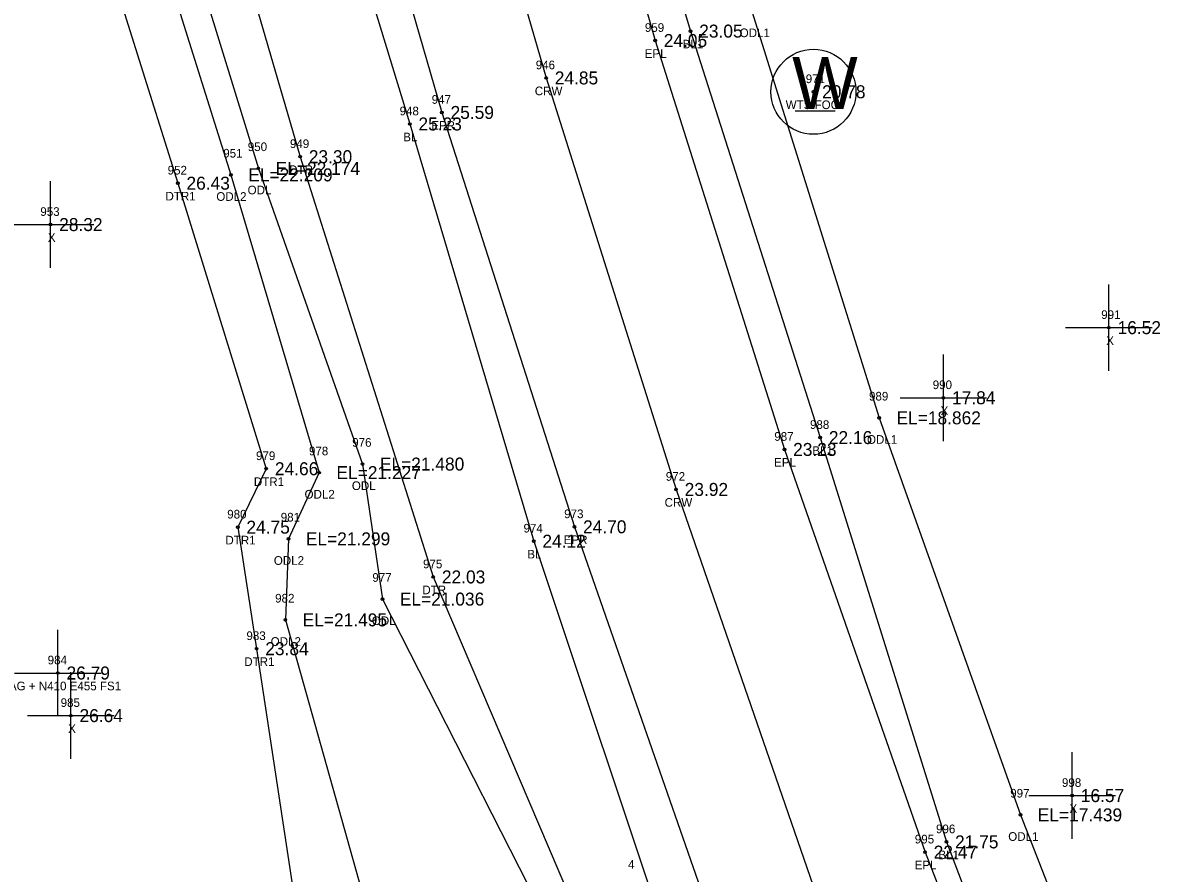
# Model space of a CAD drawing. Extents: x 2042211 to 2045853, y 303080 to 309569.
# Drawn here: x 2042861.3 to 2042993, y 306702 to 306800.2 of the extents above; entities that cross this region are included whole.
import ezdxf

# ---------------------------------------------------------------- set-up
doc = ezdxf.new("R2010")
doc.units = 0
for name, color, linetype in [('BR_500YR_SCOUR', 7, 'Continuous'), ('RD_DTM_BkLn1', 7, 'Continuous'), ('RD_DTM_BkLn_txCode', 7, 'Continuous'), ('RD_EX_H2O', 7, 'Continuous'), ('RD_EX_H2O_txCode', 7, 'Continuous'), ('RD_EX_Misc', 7, 'Continuous'), ('RD_EX_Misc_txCode', 7, 'Continuous'), ('RD_EX_Road', 7, 'Continuous'), ('RD_EX_Road_txCode', 7, 'Continuous'), ('RD_EX_TX_H2O_ELEV', 7, 'Continuous'), ('RD_EX_TX_Misc_ELEV', 7, 'Continuous'), ('RD_EX_TX_Road_ELEV', 7, 'Continuous'), ('RD_EX_TX_UT_ELEV', 7, 'Continuous'), ('RD_EX_UT_txCode', 7, 'Continuous'), ('RD_HC_Survey_ELEV', 7, 'Continuous'), ('RD_HC_Survey_txCode', 7, 'Continuous'), ('RD_SMD_Locator', 7, 'Continuous')]:
    doc.layers.add(name, color=color, linetype=linetype)

msp = doc.modelspace()

# ---------------------------------------------------------------- linework, layer by layer
at = {"layer": 'BR_500YR_SCOUR'}
msp.add_line((2042950.59, 306790.07), (2042955.22, 306790.07), dxfattribs=at)
for radius in [4.91, 0.15]:
    msp.add_circle((2042952.72, 306792.28), radius, dxfattribs=at)
at = {"layer": 'RD_DTM_BkLn1'}
for points in [[(2042839.81, 307329.37), (2042840.93, 307280.46), (2042843.39, 307231.17), (2042846.87, 307181.66), (2042851.76, 307132.07), (2042857.83, 307083.36), (2042865.03, 307034.36), (2042873.56, 306985.67), (2042883.71, 306937.59), (2042895.32, 306889.27), (2042908.01, 306841.41), (2042921.81, 306793.88), (2042936.83, 306746.34), (2042953.05, 306699.55), (2042970.36, 306653.6), (2042989.25, 306607.34), (2043009.36, 306561.99), (2043030.44, 306517.39), (2043052.89, 306472.91), (2043076.3, 306429.26), (2043100.43, 306386.21)], [(2042857.66, 307329.64), (2042861.09, 307281.84), (2042862.27, 307232.19), (2042866.29, 307183.84), (2042870.56, 307134.28), (2042875.48, 307086.26), (2042882.95, 307037.68), (2042891.21, 306988.93), (2042900.82, 306941.19), (2042911.81, 306893.75), (2042924.4, 306846), (2042938.51, 306799.29), (2042953.5, 306752.33), (2042968.09, 306705.62), (2042985.63, 306659.36), (2043004.49, 306613.62), (2043024.61, 306569.26), (2043045.97, 306525.25), (2043068.43, 306480.84), (2043092.42, 306438.64), (2043116.55, 306395.12)], [(2042839.17, 307095.11), (2042841.19, 307080.52), (2042848.71, 307031.33), (2042857.64, 306982.34), (2042868.25, 306933.78), (2042879.62, 306884.9), (2042891.37, 306836.61), (2042906.05, 306788.56), (2042920.38, 306740.36), (2042936.3, 306692.68), (2042942.2, 306670.77), (2042952.72, 306646.49), (2042972.88, 306600.44), (2042993.94, 306554.96), (2043015.19, 306509.48), (2043037.06, 306464.5), (2043060.22, 306420.45)]]:
    msp.add_lwpolyline(points, dxfattribs=at)
at = {"layer": 'RD_EX_H2O'}
for points in [[(2042866.82, 307329.93), (2042876.23, 307282.16), (2042878.43, 307232.86), (2042875.08, 307184.77), (2042887.19, 307136.65), (2042884.32, 307120.02), (2042882.74, 307087.49), (2042892.51, 307039.16), (2042896.41, 306990.42), (2042899.37, 306973.37), (2042910.05, 306942.23), (2042920.75, 306896.67), (2042927.15, 306846.78), (2042945.6, 306801.59), (2042960.32, 306754.61), (2042976.65, 306708.74), (2042994.63, 306662.76), (2043013.3, 306616.98), (2043029.17, 306571.91), (2043050.77, 306528.53)], [(2042809.74, 307126.16), (2042806.56, 307122.63), (2042790.31, 307116.78), (2042788.49, 307114.78), (2042791.89, 307113.57), (2042804.81, 307114.94), (2042810.25, 307075.93), (2042820.25, 307025.92), (2042830.4, 306977.21), (2042843.29, 306928.12), (2042852.91, 306878.24), (2042864.55, 306828.43), (2042879.23, 306781.72), (2042889.45, 306748.73), (2042886.16, 306741.98), (2042888.34, 306727.94), (2042896.13, 306676.35), (2042885.67, 306665.43), (2042857.25, 306612.72)], [(2042809.74, 307126.16), (2042815.01, 307124.31), (2042821.79, 307118.99), (2042825.8, 307110.2), (2042827.88, 307100.21), (2042830.08, 307078.71), (2042836.25, 307029.11), (2042845.48, 306980.04), (2042852.07, 306929.46), (2042864.58, 306881.26), (2042879.31, 306833.06), (2042893.37, 306784.78), (2042908.76, 306736.23), (2042928.77, 306689.39), (2042938.94, 306669.11)], [(2042810.02, 307117.36), (2042813.87, 307076.18), (2042825.65, 307027), (2042835.99, 306978.45), (2042846.19, 306929.27), (2042857.5, 306879.97), (2042870.3, 306830.67), (2042885.37, 306782.68), (2042895.57, 306748.28), (2042892.03, 306740.63), (2042891.66, 306731.27), (2042905.95, 306680.58), (2042906.87, 306643.18), (2042864.97, 306605.63)], [(2042812.2, 307117.75), (2042817.66, 307076.99), (2042828.97, 307027.39), (2042840.42, 306978.95), (2042848.44, 306929.66), (2042859.84, 306880.36), (2042873.68, 306831.67), (2042888.54, 306783.43), (2042900.59, 306749.27), (2042902.9, 306733.67), (2042926.04, 306688.21), (2042936.45, 306668.37), (2042947.44, 306643.99), (2042966.18, 306597.91), (2042985.34, 306551.14), (2042987.61, 306538.59)]]:
    msp.add_lwpolyline(points, dxfattribs=at)
at = {"layer": 'RD_EX_Misc'}
for p, q in [((2042864.51, 306771.94), (2042864.51, 306781.94)), ((2042859.51, 306776.94), (2042869.51, 306776.94)), ((2042986.88, 306760.03), (2042986.88, 306770.03)), ((2042981.88, 306765.03), (2042991.88, 306765.03)), ((2042967.74, 306751.93), (2042967.74, 306761.93)), ((2042962.74, 306756.93), (2042972.74, 306756.93)), ((2042865.36, 306720.13), (2042865.36, 306730.13)), ((2042860.36, 306725.13), (2042870.36, 306725.13)), ((2042866.86, 306715.21), (2042866.86, 306725.21)), ((2042861.86, 306720.21), (2042871.86, 306720.21)), ((2042982.63, 306705.97), (2042982.63, 306715.97)), ((2042977.63, 306710.97), (2042987.63, 306710.97))]:
    msp.add_line(p, q, dxfattribs=at)
at = {"layer": 'RD_EX_Road'}
for points in [[(2042853.31, 307329.44), (2042854.43, 307281.38), (2042857.15, 307232.07), (2042860.27, 307183.35), (2042865.16, 307133.89), (2042871.37, 307085.7), (2042878.53, 307037.13), (2042886.97, 306988.21), (2042897.02, 306940.01), (2042908.28, 306892.66), (2042921.09, 306844.85), (2042934.41, 306798.2), (2042949.37, 306750.96), (2042965.62, 306704.44), (2042983.48, 306658.43), (2043001.91, 306612.18), (2043021.64, 306567.98), (2043042.58, 306523.81), (2043065.05, 306479.23), (2043088.14, 306436.09), (2043112.53, 306392.81)], [(2042895.94, 306837.56), (2042909.76, 306789.89), (2042925.08, 306742.02), (2042941.49, 306695.02), (2042958.75, 306648.66), (2042978.01, 306602.25), (2042998.08, 306556.93), (2043019.38, 306511.63), (2043041.84, 306466.86), (2043065.03, 306422.83)]]:
    msp.add_lwpolyline(points, dxfattribs=at)
at = {"layer": 'RD_SMD_Locator'}
for centre in [(2042938.51, 306799.29), (2042934.41, 306798.2), (2042921.81, 306793.88), (2042909.76, 306789.89), (2042906.05, 306788.56), (2042893.37, 306784.78), (2042888.54, 306783.43), (2042879.23, 306781.72), (2042885.37, 306782.68), (2042864.51, 306776.94), (2042986.88, 306765.03), (2042967.74, 306756.93), (2042960.32, 306754.61), (2042953.5, 306752.33), (2042949.37, 306750.96), (2042900.59, 306749.27), (2042889.45, 306748.73), (2042895.57, 306748.28), (2042936.83, 306746.34), (2042886.16, 306741.98), (2042925.08, 306742.02), (2042892.03, 306740.63), (2042920.38, 306740.36), (2042908.76, 306736.23), (2042902.9, 306733.67), (2042891.66, 306731.27), (2042888.34, 306727.94), (2042865.36, 306725.13), (2042866.86, 306720.21), (2042982.63, 306710.97), (2042976.65, 306708.74), (2042968.09, 306705.62), (2042965.62, 306704.44)]:
    msp.add_circle(centre, 0.15, dxfattribs=at)

# ---------------------------------------------------------------- texts
at = {"layer": 'BR_500YR_SCOUR'}
msp.add_text('W', height=6, dxfattribs=at).set_placement((2042950.26, 306790.28))
at = {"layer": 'RD_DTM_BkLn_txCode'}
for s, p in [('BL1', (2042937.59, 306797.29)), ('948', (2042904.87, 306789.56)), ('BL', (2042905.29, 306786.56)), ('988', (2042952.32, 306753.33)), ('BL1', (2042952.58, 306750.33)), ('974', (2042919.2, 306741.36)), ('BL', (2042919.63, 306738.36)), ('996', (2042966.89, 306706.62)), ('BL1', (2042967.17, 306703.62))]:
    msp.add_text(s, height=1, dxfattribs=at).set_placement(p)
at = {"layer": 'RD_EX_H2O_txCode'}
for s, p in [('ODL1', (2042944.19, 306798.59)), ('950', (2042887.32, 306785.43)), ('949', (2042892.19, 306785.78)), ('951', (2042884.48, 306784.68)), ('952', (2042878.05, 306782.72)), ('DTR', (2042892.1, 306782.78)), ('DTR1', (2042877.8, 306779.72)), ('ODL2', (2042883.68, 306779.68)), ('ODL', (2042887.3, 306780.43)), ('989', (2042959.14, 306756.61)), ('976', (2042899.39, 306751.27)), ('ODL1', (2042958.91, 306751.61)), ('979', (2042888.27, 306749.73)), ('978', (2042894.39, 306750.28)), ('DTR1', (2042888.02, 306746.73)), ('ODL', (2042899.35, 306746.27)), ('ODL2', (2042893.88, 306745.28)), ('980', (2042884.94, 306742.98)), ('981', (2042891.13, 306742.63)), ('DTR1', (2042884.73, 306739.98)), ('ODL2', (2042890.33, 306737.63)), ('975', (2042907.58, 306737.23)), ('977', (2042901.72, 306735.67)), ('DTR', (2042907.5, 306734.23)), ('982', (2042890.48, 306733.27)), ('ODL', (2042901.66, 306730.67)), ('983', (2042887.16, 306728.94)), ('ODL2', (2042889.97, 306728.27)), ('DTR1', (2042886.91, 306725.94)), ('997', (2042975.47, 306710.74)), ('ODL1', (2042975.24, 306705.74))]:
    msp.add_text(s, height=1, dxfattribs=at).set_placement(p)
at = {"layer": 'RD_EX_Misc_txCode'}
for s, p in [('953', (2042863.33, 306777.94)), ('X', (2042864.2, 306774.94)), ('991', (2042985.99, 306766.03)), ('X', (2042986.57, 306763.03)), ('990', (2042966.51, 306757.93)), ('X', (2042967.42, 306754.93)), ('984', (2042864.18, 306726.13)), ('MSP FLAG + N410 E455 FS1', (2042854.87, 306723.13)), ('985', (2042865.68, 306721.21)), ('X', (2042866.55, 306718.21)), ('998', (2042981.45, 306711.97)), ('X', (2042982.32, 306708.97))]:
    msp.add_text(s, height=1, dxfattribs=at).set_placement(p)
at = {"layer": 'RD_EX_Road_txCode'}
for s, p in [('959', (2042933.23, 306799.2)), ('EPL', (2042933.21, 306796.2)), ('947', (2042908.58, 306790.89)), ('EPR', (2042908.53, 306787.89)), ('987', (2042948.19, 306751.96)), ('EPL', (2042948.17, 306748.96)), ('973', (2042923.9, 306743.02)), ('EPR', (2042923.85, 306740.02)), ('995', (2042964.44, 306705.44)), ('EPL', (2042964.42, 306702.44))]:
    msp.add_text(s, height=1, dxfattribs=at).set_placement(p)
at = {"layer": 'RD_EX_TX_H2O_ELEV'}
for s, p in [('23.30', (2042894.37, 306784.03)), ('EL=22.209', (2042887.37, 306781.93)), ('EL=22.174', (2042890.54, 306782.68)), ('26.43', (2042880.23, 306780.97)), ('EL=18.862', (2042962.32, 306753.86)), ('24.66', (2042890.45, 306747.98)), ('EL=21.227', (2042897.57, 306747.53)), ('EL=21.480', (2042902.59, 306748.52)), ('24.75', (2042887.16, 306741.23)), ('EL=21.299', (2042894.03, 306739.88)), ('22.03', (2042909.76, 306735.48)), ('EL=21.036', (2042904.9, 306732.92)), ('EL=21.495', (2042893.66, 306730.52)), ('23.84', (2042889.34, 306727.19)), ('EL=17.439', (2042978.65, 306707.99))]:
    msp.add_text(s, height=1.5, dxfattribs=at).set_placement(p)
at = {"layer": 'RD_EX_TX_Misc_ELEV'}
for s, p in [('23.05', (2042939.51, 306798.54)), ('25.23', (2042907.05, 306787.81)), ('28.32', (2042865.51, 306776.19)), ('16.52', (2042987.88, 306764.28)), ('17.84', (2042968.74, 306756.18)), ('22.16', (2042954.5, 306751.58)), ('24.12', (2042921.38, 306739.61)), ('26.79', (2042866.36, 306724.38)), ('26.64', (2042867.86, 306719.46)), ('16.57', (2042983.63, 306710.22)), ('21.75', (2042969.09, 306704.87))]:
    msp.add_text(s, height=1.5, dxfattribs=at).set_placement(p)
at = {"layer": 'RD_EX_TX_Road_ELEV'}
for s, p in [('24.05', (2042935.41, 306797.45)), ('25.59', (2042910.76, 306789.14)), ('23.23', (2042950.37, 306750.21)), ('24.70', (2042926.08, 306741.27)), ('22.47', (2042966.62, 306703.69))]:
    msp.add_text(s, height=1.5, dxfattribs=at).set_placement(p)
at = {"layer": 'RD_EX_TX_UT_ELEV'}
msp.add_text('20.78', height=1.5, dxfattribs=at).set_placement((2042953.72, 306791.53))
at = {"layer": 'RD_EX_UT_txCode'}
for s, p in [('971', (2042951.83, 306793.28)), ('WTS FOC', (2042949.51, 306790.28))]:
    msp.add_text(s, height=1, dxfattribs=at).set_placement(p)
at = {"layer": 'RD_HC_Survey_ELEV'}
for s, p in [('24.85', (2042922.81, 306793.13)), ('23.92', (2042937.83, 306745.59))]:
    msp.add_text(s, height=1.5, dxfattribs=at).set_placement(p)
at = {"layer": 'RD_HC_Survey_txCode'}
for s, p in [('946', (2042920.61, 306794.88)), ('CRW', (2042920.5, 306791.88)), ('972', (2042935.65, 306747.34)), ('CRW', (2042935.51, 306744.34)), ('4', (2042931.29, 306702.52))]:
    msp.add_text(s, height=1, dxfattribs=at).set_placement(p)

doc.saveas('drawing.dxf')
